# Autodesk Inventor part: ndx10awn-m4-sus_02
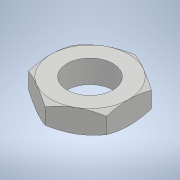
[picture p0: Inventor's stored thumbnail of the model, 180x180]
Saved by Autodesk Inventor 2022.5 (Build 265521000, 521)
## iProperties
Part Number: ndx10awn-m4-sus_02
Material: 一般
Document SubType Name: Modeling
Designer: ImaoCorp
Density: 1 g/cm^3
Appearance: 既定
Author: ImaoCorp
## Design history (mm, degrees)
feature "ndx10awn-m4-sus_02"
node "ソリッド1"
